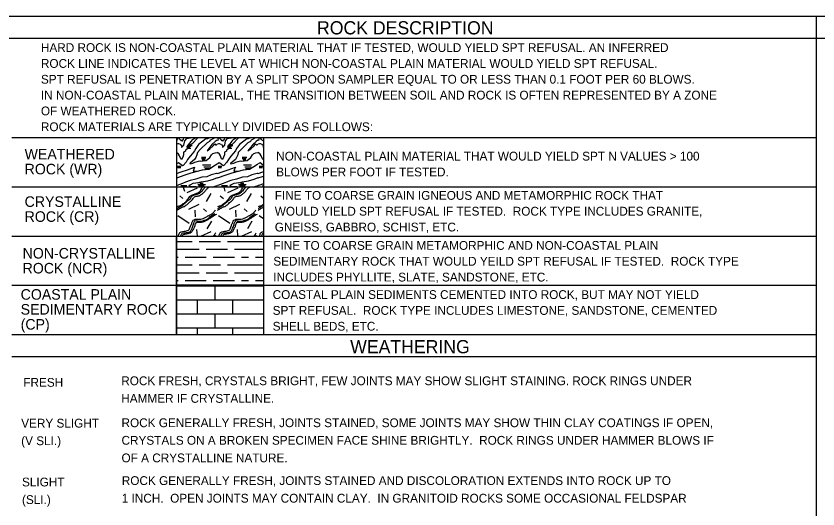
# Model space of a CAD drawing. Extents: x 278710 to 279187, y 171464 to 171625.
# Drawn here: x 279081.88 to 279121.42, y 171541.71 to 171566.02 of the extents above; entities that cross this region are included whole.
import ezdxf

# ---------------------------------------------------------------- set-up
doc = ezdxf.new("R2010")
doc.units = 0
doc.layers.add('Prop Strc Sect_ Misc - User Comment (Tx - small)', color=7, linetype='Continuous')

msp = doc.modelspace()

# ---------------------------------------------------------------- linework, layer by layer
at = {"layer": 'Prop Strc Sect_ Misc - User Comment (Tx - small)'}
for p, q in [((279005.33, 171566.02), (279158.027, 171566.02)), ((279121.332, 171566.02), (279121.332, 171485.806)), ((279005.33, 171564.936), (279158.027, 171564.936)), ((279121.332, 171560.012), (279081.678, 171560.012)), ((279089.795, 171560.012), (279089.795, 171550.295)), ((279090.164, 171560.005), (279090.167, 171560.012)), ((279090.484, 171560.005), (279090.492, 171560.012)), ((279090.844, 171560.005), (279090.853, 171560.012)), ((279092.176, 171560.005), (279092.179, 171560.012)), ((279092.496, 171560.005), (279092.504, 171560.012)), ((279092.856, 171560.005), (279092.865, 171560.012)), ((279094.081, 171560.012), (279094.081, 171550.295)), ((279090.31, 171559.559), (279090.458, 171559.559)), ((279090.323, 171559.603), (279090.495, 171559.603)), ((279090.324, 171559.51), (279090.504, 171559.51)), ((279090.348, 171559.641), (279090.562, 171559.641)), ((279092.322, 171559.559), (279092.47, 171559.559)), ((279092.335, 171559.603), (279092.507, 171559.603)), ((279092.336, 171559.51), (279092.516, 171559.51)), ((279092.36, 171559.641), (279092.574, 171559.641)), ((279091.024, 171559.06), (279091.244, 171559.06)), ((279091.024, 171558.993), (279091.224, 171558.993)), ((279091.064, 171558.925), (279091.204, 171558.925)), ((279093.036, 171559.06), (279093.256, 171559.06)), ((279093.036, 171558.993), (279093.236, 171558.993)), ((279093.076, 171558.925), (279093.216, 171558.925)), ((279089.844, 171558.61), (279090.024, 171558.61)), ((279089.844, 171558.543), (279090.004, 171558.543)), ((279091.084, 171558.678), (279091.484, 171558.678)), ((279091.144, 171558.588), (279091.464, 171558.588)), ((279091.184, 171558.498), (279091.404, 171558.498)), ((279091.856, 171558.61), (279092.036, 171558.61)), ((279091.856, 171558.543), (279092.016, 171558.543)), ((279093.096, 171558.678), (279093.496, 171558.678)), ((279093.156, 171558.588), (279093.476, 171558.588)), ((279093.196, 171558.498), (279093.416, 171558.498)), ((279093.868, 171558.61), (279094.048, 171558.61)), ((279093.868, 171558.543), (279094.028, 171558.543)), ((279090.844, 171557.719), (279091.219, 171557.719)), ((279090.944, 171557.778), (279091.104, 171557.778)), ((279092.856, 171557.719), (279093.231, 171557.719)), ((279092.956, 171557.778), (279093.116, 171557.778)), ((279121.332, 171557.583), (279081.678, 171557.583)), ((279089.985, 171557.604), (279090.379, 171557.604)), ((279090.004, 171557.665), (279090.304, 171557.665)), ((279090.884, 171557.643), (279091.164, 171557.643)), ((279091.997, 171557.604), (279092.391, 171557.604)), ((279092.016, 171557.665), (279092.316, 171557.665)), ((279092.896, 171557.643), (279093.176, 171557.643)), ((279094.009, 171557.604), (279094.081, 171557.604)), ((279094.028, 171557.665), (279094.081, 171557.665)), ((279094.081, 171556.679), (279093.977, 171556.614)), ((279121.332, 171555.154), (279081.678, 171555.154)), ((279091.725, 171555.218), (279091.691, 171555.158)), ((279093.725, 171555.218), (279093.691, 171555.158)), ((279094.081, 171555.187), (279094.065, 171555.158)), ((279089.791, 171554.902), (279089.877, 171554.902)), ((279089.877, 171554.902), (279090.571, 171554.902)), ((279090.918, 171554.902), (279091.96, 171554.902)), ((279092.307, 171554.902), (279093.348, 171554.902)), ((279093.348, 171554.902), (279094.042, 171554.902)), ((279089.791, 171554.52), (279089.877, 171554.52)), ((279089.877, 171554.52), (279090.918, 171554.52)), ((279091.265, 171554.52), (279092.307, 171554.52)), ((279092.654, 171554.52), (279093.348, 171554.52)), ((279093.348, 171554.52), (279094.076, 171554.52)), ((279089.791, 171554.134), (279089.873, 171554.134)), ((279089.791, 171553.748), (279089.877, 171553.748)), ((279089.877, 171553.748), (279090.571, 171553.748)), ((279090.22, 171554.134), (279091.261, 171554.134)), ((279090.918, 171553.748), (279091.96, 171553.748)), ((279091.608, 171554.134), (279092.649, 171554.134)), ((279092.307, 171553.748), (279093.348, 171553.748)), ((279092.996, 171554.134), (279093.343, 171554.134)), ((279093.348, 171553.748), (279094.042, 171553.748)), ((279093.69, 171554.134), (279094.076, 171554.134)), ((279089.791, 171553.362), (279089.877, 171553.362)), ((279089.877, 171553.362), (279090.918, 171553.362)), ((279091.265, 171553.362), (279092.307, 171553.362)), ((279092.654, 171553.362), (279093.348, 171553.362)), ((279093.348, 171553.362), (279094.076, 171553.362)), ((279089.791, 171552.976), (279089.873, 171552.976)), ((279090.22, 171552.976), (279091.261, 171552.976)), ((279091.608, 171552.976), (279092.649, 171552.976)), ((279092.996, 171552.976), (279093.343, 171552.976)), ((279093.69, 171552.976), (279094.076, 171552.976)), ((279121.332, 171552.724), (279081.678, 171552.724)), ((279091.704, 171552.026), (279091.704, 171552.711)), ((279089.795, 171552.026), (279094.081, 171552.026)), ((279090.836, 171551.332), (279090.836, 171552.026)), ((279092.571, 171551.332), (279092.571, 171552.026)), ((279089.795, 171551.332), (279094.081, 171551.332)), ((279091.704, 171550.638), (279091.704, 171551.332)), ((279089.795, 171550.638), (279094.081, 171550.638)), ((279090.836, 171550.295), (279090.836, 171550.638)), ((279092.571, 171550.295), (279092.571, 171550.638)), ((279121.332, 171550.295), (279081.678, 171550.295)), ((279121.332, 171549.21), (279081.678, 171549.21))]:
    msp.add_line(p, q, dxfattribs=at)
for points in [[(279089.8, 171559.897), (279089.85, 171559.925), (279089.841, 171559.984), (279089.831, 171560.012)], [(279089.987, 171559.685), (279089.909, 171559.724), (279089.855, 171559.724), (279089.8, 171559.7)], [(279090.844, 171560.005), (279090.564, 171559.713), (279090.504, 171559.668), (279090.364, 171559.668), (279090.304, 171559.578), (279090.324, 171559.51), (279090.344, 171559.465), (279090.244, 171559.398), (279090.244, 171559.353), (279090.244, 171559.353), (279090.184, 171559.33), (279090.144, 171559.308), (279090.144, 171559.173), (279090.104, 171559.06), (279090.044, 171558.948), (279090.004, 171558.97), (279089.944, 171559.128), (279089.898, 171559.213)], [(279089.964, 171559.938), (279089.924, 171559.983), (279089.924, 171560.012)], [(279089.964, 171559.938), (279089.984, 171559.915), (279090.024, 171559.87), (279090.044, 171559.915), (279090.064, 171559.87), (279090.084, 171559.87), (279090.104, 171559.915), (279090.144, 171559.938), (279090.164, 171560.005)], [(279091.244, 171559.96), (279090.884, 171559.69), (279090.744, 171559.488), (279090.684, 171559.375), (279090.584, 171559.24), (279090.464, 171559.105), (279090.344, 171558.948), (279090.264, 171558.813), (279090.124, 171558.655), (279090.084, 171558.633), (279089.964, 171558.723)], [(279089.987, 171559.685), (279090.044, 171559.645), (279090.044, 171559.533), (279090.164, 171559.645), (279090.204, 171559.87), (279090.304, 171559.983), (279090.484, 171560.005)], [(279090.728, 171560.012), (279090.699, 171559.986), (279090.661, 171559.967), (279090.571, 171559.91), (279090.512, 171559.849), (279090.421, 171559.739), (279090.364, 171559.668)], [(279091.324, 171559.78), (279090.964, 171559.443), (279090.824, 171559.285), (279090.804, 171559.173), (279090.744, 171559.038), (279090.684, 171558.948), (279090.464, 171558.768), (279090.444, 171558.745), (279090.464, 171558.723), (279090.604, 171558.768), (279090.704, 171558.813), (279090.944, 171558.88), (279090.964, 171558.858), (279091.264, 171558.903), (279091.444, 171559.038), (279091.522, 171559.178)], [(279091.244, 171559.96), (279091.282, 171559.975), (279091.338, 171559.987), (279091.407, 171560.009), (279091.411, 171560.012)], [(279091.8, 171559.897), (279091.704, 171559.825), (279091.544, 171559.69), (279091.444, 171559.555), (279091.304, 171559.375), (279091.444, 171559.465), (279091.604, 171559.623), (279091.684, 171559.713), (279091.724, 171559.668), (279091.764, 171559.668), (279091.8, 171559.7)], [(279091.324, 171559.78), (279091.444, 171559.848), (279091.484, 171559.915), (279091.604, 171559.983), (279091.644, 171560.005)], [(279091.644, 171560.005), (279091.658, 171560.012)], [(279091.812, 171559.897), (279091.862, 171559.925), (279091.853, 171559.984), (279091.843, 171560.012)], [(279091.999, 171559.685), (279091.921, 171559.724), (279091.867, 171559.724), (279091.812, 171559.7)], [(279092.856, 171560.005), (279092.576, 171559.713), (279092.516, 171559.668), (279092.376, 171559.668), (279092.316, 171559.578), (279092.336, 171559.51), (279092.356, 171559.465), (279092.256, 171559.398), (279092.256, 171559.353), (279092.256, 171559.353), (279092.196, 171559.33), (279092.156, 171559.308), (279092.156, 171559.173), (279092.116, 171559.06), (279092.056, 171558.948), (279092.016, 171558.97), (279091.956, 171559.128), (279091.91, 171559.213)], [(279091.976, 171559.938), (279091.936, 171559.983), (279091.936, 171560.012)], [(279091.976, 171559.938), (279091.996, 171559.915), (279092.036, 171559.87), (279092.056, 171559.915), (279092.076, 171559.87), (279092.096, 171559.87), (279092.116, 171559.915), (279092.156, 171559.938), (279092.176, 171560.005)], [(279093.256, 171559.96), (279092.896, 171559.69), (279092.756, 171559.488), (279092.696, 171559.375), (279092.596, 171559.24), (279092.476, 171559.105), (279092.356, 171558.948), (279092.276, 171558.813), (279092.136, 171558.655), (279092.096, 171558.633), (279091.976, 171558.723)], [(279091.999, 171559.685), (279092.056, 171559.645), (279092.056, 171559.533), (279092.176, 171559.645), (279092.216, 171559.87), (279092.316, 171559.983), (279092.496, 171560.005)], [(279092.74, 171560.012), (279092.711, 171559.986), (279092.673, 171559.967), (279092.583, 171559.91), (279092.524, 171559.849), (279092.433, 171559.739), (279092.376, 171559.668)], [(279093.336, 171559.78), (279092.976, 171559.443), (279092.836, 171559.285), (279092.816, 171559.173), (279092.756, 171559.038), (279092.696, 171558.948), (279092.476, 171558.768), (279092.456, 171558.745), (279092.476, 171558.723), (279092.616, 171558.768), (279092.716, 171558.813), (279092.956, 171558.88), (279092.976, 171558.858), (279093.276, 171558.903), (279093.456, 171559.038), (279093.534, 171559.178)], [(279093.256, 171559.96), (279093.294, 171559.975), (279093.35, 171559.987), (279093.419, 171560.009), (279093.423, 171560.012)], [(279093.812, 171559.897), (279093.716, 171559.825), (279093.556, 171559.69), (279093.456, 171559.555), (279093.316, 171559.375), (279093.456, 171559.465), (279093.616, 171559.623), (279093.696, 171559.713), (279093.736, 171559.668), (279093.776, 171559.668), (279093.812, 171559.7)], [(279093.336, 171559.78), (279093.456, 171559.848), (279093.496, 171559.915), (279093.616, 171559.983), (279093.656, 171560.005)], [(279093.656, 171560.005), (279093.67, 171560.012)], [(279093.824, 171559.897), (279093.874, 171559.925), (279093.865, 171559.984), (279093.855, 171560.012)], [(279094.011, 171559.685), (279093.933, 171559.724), (279093.879, 171559.724), (279093.824, 171559.7)], [(279093.988, 171559.938), (279093.948, 171559.983), (279093.948, 171560.012)], [(279093.988, 171559.938), (279094.008, 171559.915), (279094.048, 171559.87), (279094.068, 171559.915), (279094.081, 171559.885)], [(279094.011, 171559.685), (279094.068, 171559.645), (279094.068, 171559.533), (279094.081, 171559.545)], [(279089.898, 171559.213), (279089.799, 171559.293)], [(279091.522, 171559.178), (279091.588, 171559.244), (279091.701, 171559.274), (279091.799, 171559.293)], [(279091.91, 171559.213), (279091.811, 171559.293)], [(279093.534, 171559.178), (279093.6, 171559.244), (279093.713, 171559.274), (279093.811, 171559.293)], [(279093.922, 171559.213), (279093.823, 171559.293)], [(279094.081, 171558.972), (279094.068, 171558.948), (279094.028, 171558.97), (279093.968, 171559.128), (279093.922, 171559.213)], [(279089.964, 171558.723), (279089.89, 171558.779), (279089.8, 171558.733)], [(279089.8, 171558.259), (279090.027, 171558.338), (279090.33, 171558.436), (279090.687, 171558.559), (279090.643, 171558.461), (279090.609, 171558.377), (279090.829, 171558.373)], [(279089.804, 171558.048), (279090.224, 171558.183), (279090.524, 171558.295), (279091.084, 171558.43), (279091.384, 171558.475), (279091.724, 171558.678), (279091.8, 171558.733)], [(279091.976, 171558.723), (279091.902, 171558.779), (279091.812, 171558.733)], [(279091.812, 171558.259), (279092.039, 171558.338), (279092.342, 171558.436), (279092.699, 171558.559), (279092.655, 171558.461), (279092.621, 171558.377), (279092.841, 171558.373)], [(279091.816, 171558.048), (279092.236, 171558.183), (279092.536, 171558.295), (279093.096, 171558.43), (279093.396, 171558.475), (279093.736, 171558.678), (279093.812, 171558.733)], [(279093.988, 171558.723), (279093.914, 171558.779), (279093.824, 171558.733)], [(279094.081, 171558.653), (279093.988, 171558.723)], [(279091.8, 171558.259), (279091.764, 171558.25), (279091.504, 171558.183), (279091.284, 171558.093), (279091.044, 171558.07), (279090.744, 171557.98), (279090.464, 171557.913), (279090.244, 171557.823), (279090.084, 171557.755), (279089.824, 171557.665), (279089.804, 171557.665)], [(279093.812, 171558.259), (279093.776, 171558.25), (279093.516, 171558.183), (279093.296, 171558.093), (279093.056, 171558.07), (279092.756, 171557.98), (279092.476, 171557.913), (279092.256, 171557.823), (279092.096, 171557.755), (279091.836, 171557.665), (279091.816, 171557.665)], [(279093.824, 171558.259), (279094.051, 171558.338), (279094.081, 171558.347)], [(279093.828, 171558.048), (279094.081, 171558.129)], [(279089.795, 171558.05), (279089.799, 171558.052)], [(279090.822, 171557.8), (279090.744, 171557.778), (279090.604, 171557.755), (279090.484, 171557.688), (279090.404, 171557.665), (279090.424, 171557.643), (279090.524, 171557.62), (279090.704, 171557.62), (279090.764, 171557.62), (279090.78, 171557.583)], [(279090.822, 171557.8), (279091.013, 171557.841), (279091.332, 171557.9), (279091.616, 171557.973), (279091.811, 171558.052)], [(279092.834, 171557.8), (279092.756, 171557.778), (279092.616, 171557.755), (279092.496, 171557.688), (279092.416, 171557.665), (279092.436, 171557.643), (279092.536, 171557.62), (279092.716, 171557.62), (279092.776, 171557.62), (279092.792, 171557.583)], [(279092.834, 171557.8), (279093.025, 171557.841), (279093.344, 171557.9), (279093.628, 171557.973), (279093.823, 171558.052)], [(279094.081, 171557.745), (279093.848, 171557.665), (279093.828, 171557.665)], [(279090.122, 171557.583), (279090.185, 171557.386)], [(279090.324, 171557.319), (279090.832, 171557.555)], [(279091.571, 171557.583), (279091.65, 171557.606), (279091.804, 171557.665)], [(279092.122, 171557.583), (279092.185, 171557.386)], [(279092.324, 171557.319), (279092.832, 171557.555)], [(279093.583, 171557.583), (279093.662, 171557.606), (279093.816, 171557.665)], [(279089.954, 171557.151), (279090.11, 171557.015)], [(279091.482, 171557.265), (279091.254, 171556.877)], [(279091.954, 171557.151), (279092.11, 171557.015)], [(279093.482, 171557.265), (279093.254, 171556.877)], [(279093.954, 171557.151), (279094.081, 171557.04)], [(279090.402, 171556.503), (279090.91, 171556.739)], [(279091.124, 171556.518), (279091.28, 171556.382)], [(279092.402, 171556.503), (279092.91, 171556.739)], [(279093.124, 171556.518), (279093.28, 171556.382)], [(279089.867, 171556.186), (279090.423, 171555.802)], [(279090.696, 171556.451), (279090.72, 171556.119)], [(279091.867, 171556.186), (279092.423, 171555.802)], [(279092.696, 171556.451), (279092.72, 171556.119)], [(279093.867, 171556.186), (279094.081, 171556.038)], [(279091.516, 171555.911), (279091.288, 171555.523)], [(279093.516, 171555.911), (279093.288, 171555.523)], [(279090.783, 171555.488), (279090.807, 171555.158)], [(279091, 171555.159), (279091.508, 171555.395)], [(279092.783, 171555.488), (279092.807, 171555.158)], [(279093, 171555.159), (279093.508, 171555.395)]]:
    msp.add_lwpolyline(points, dxfattribs=at)
for points in [[(279089.791, 171555.158), (279094.076, 171555.158), (279094.076, 171552.742), (279089.791, 171552.742)], [(279089.795, 171552.711), (279094.081, 171552.711), (279094.081, 171550.295), (279089.795, 171550.295)]]:
    msp.add_lwpolyline(points, close=True, dxfattribs=at)
for points in [[(279089.837, 171556.63), (279089.997, 171556.682), (279090.165, 171556.798), (279090.289, 171556.906), (279090.313, 171556.942), (279090.393, 171557.026), (279090.445, 171557.118), (279090.545, 171557.19), (279090.637, 171557.226), (279090.797, 171557.282), (279090.893, 171557.33), (279091.001, 171557.45), (279091.049, 171557.55), (279091.071, 171557.583)], [(279091.188, 171557.583), (279091.157, 171557.522), (279091.077, 171557.43), (279091.005, 171557.342), (279090.893, 171557.258), (279090.793, 171557.214), (279090.673, 171557.178), (279090.605, 171557.162), (279090.529, 171557.114), (279090.505, 171557.066), (279090.461, 171556.99), (279090.337, 171556.898), (279090.253, 171556.822), (279090.177, 171556.754), (279090.085, 171556.682), (279089.977, 171556.614)], [(279090.133, 171556.606), (279090.301, 171556.714), (279090.449, 171556.85), (279090.589, 171556.978), (279090.689, 171557.11), (279090.829, 171557.142), (279090.981, 171557.19), (279091.101, 171557.282), (279091.205, 171557.378), (279091.253, 171557.454)], [(279091.253, 171557.454), (279091.349, 171557.546), (279091.404, 171557.583)], [(279091.837, 171556.63), (279091.997, 171556.682), (279092.165, 171556.798), (279092.289, 171556.906), (279092.313, 171556.942), (279092.393, 171557.026), (279092.445, 171557.118), (279092.545, 171557.19), (279092.637, 171557.226), (279092.797, 171557.282), (279092.893, 171557.33), (279093.001, 171557.45), (279093.049, 171557.55), (279093.071, 171557.583)], [(279093.188, 171557.583), (279093.157, 171557.522), (279093.077, 171557.43), (279093.005, 171557.342), (279092.893, 171557.258), (279092.793, 171557.214), (279092.673, 171557.178), (279092.605, 171557.162), (279092.529, 171557.114), (279092.505, 171557.066), (279092.461, 171556.99), (279092.337, 171556.898), (279092.253, 171556.822), (279092.177, 171556.754), (279092.085, 171556.682), (279091.977, 171556.614)], [(279092.133, 171556.606), (279092.301, 171556.714), (279092.449, 171556.85), (279092.589, 171556.978), (279092.689, 171557.11), (279092.829, 171557.142), (279092.981, 171557.19), (279093.101, 171557.282), (279093.205, 171557.378), (279093.253, 171557.454)], [(279093.253, 171557.454), (279093.349, 171557.546), (279093.404, 171557.583)], [(279089.977, 171556.614), (279089.877, 171556.554), (279089.817, 171556.51)], [(279090.133, 171556.606), (279089.977, 171556.53), (279089.817, 171556.434)], [(279091.977, 171556.614), (279091.877, 171556.554), (279091.817, 171556.51)], [(279092.133, 171556.606), (279091.977, 171556.53), (279091.817, 171556.434)], [(279093.977, 171556.614), (279093.877, 171556.554), (279093.817, 171556.51)], [(279094.081, 171556.582), (279093.977, 171556.53), (279093.817, 171556.434)], [(279093.837, 171556.63), (279093.997, 171556.682), (279094.081, 171556.735)], [(279090.545, 171555.786), (279090.557, 171555.822), (279090.617, 171555.946), (279090.717, 171555.994), (279090.905, 171556.002), (279091.065, 171556.018), (279091.209, 171556.086), (279091.345, 171556.158), (279091.529, 171556.266)], [(279090.645, 171555.786), (279090.645, 171555.798), (279090.669, 171555.854), (279090.713, 171555.918), (279090.861, 171555.906), (279091.017, 171555.91), (279091.153, 171555.946), (279091.309, 171556.006), (279091.489, 171556.15), (279091.681, 171556.282)], [(279091.768, 171556.239), (279091.568, 171556.119), (279091.444, 171556.035), (279091.308, 171555.955), (279091.176, 171555.883), (279091.012, 171555.843), (279090.864, 171555.831), (279090.792, 171555.831), (279090.744, 171555.819), (279090.724, 171555.759)], [(279091.529, 171556.266), (279091.629, 171556.346), (279091.713, 171556.458)], [(279092.545, 171555.786), (279092.557, 171555.822), (279092.617, 171555.946), (279092.717, 171555.994), (279092.905, 171556.002), (279093.065, 171556.018), (279093.209, 171556.086), (279093.345, 171556.158), (279093.529, 171556.266)], [(279092.645, 171555.786), (279092.645, 171555.798), (279092.669, 171555.854), (279092.713, 171555.918), (279092.861, 171555.906), (279093.017, 171555.91), (279093.153, 171555.946), (279093.309, 171556.006), (279093.489, 171556.15), (279093.681, 171556.282)], [(279093.768, 171556.239), (279093.568, 171556.119), (279093.444, 171556.035), (279093.308, 171555.955), (279093.176, 171555.883), (279093.012, 171555.843), (279092.864, 171555.831), (279092.792, 171555.831), (279092.744, 171555.819), (279092.724, 171555.759)], [(279093.529, 171556.266), (279093.629, 171556.346), (279093.713, 171556.458)], [(279089.876, 171555.158), (279089.901, 171555.218), (279089.965, 171555.346), (279090.089, 171555.398), (279090.241, 171555.414), (279090.421, 171555.498), (279090.485, 171555.654), (279090.545, 171555.786)], [(279089.978, 171555.158), (279090.001, 171555.19), (279090.077, 171555.31), (279090.169, 171555.322), (279090.337, 171555.346), (279090.449, 171555.374), (279090.533, 171555.498), (279090.585, 171555.614), (279090.617, 171555.71), (279090.645, 171555.786)], [(279090.725, 171555.761), (279090.721, 171555.757), (279090.693, 171555.673), (279090.625, 171555.517), (279090.549, 171555.385), (279090.465, 171555.309), (279090.353, 171555.273), (279090.213, 171555.253), (279090.149, 171555.241), (279090.093, 171555.205), (279090.065, 171555.158)], [(279091.876, 171555.158), (279091.901, 171555.218), (279091.965, 171555.346), (279092.089, 171555.398), (279092.241, 171555.414), (279092.421, 171555.498), (279092.485, 171555.654), (279092.545, 171555.786)], [(279091.978, 171555.158), (279092.001, 171555.19), (279092.077, 171555.31), (279092.169, 171555.322), (279092.337, 171555.346), (279092.449, 171555.374), (279092.533, 171555.498), (279092.585, 171555.614), (279092.617, 171555.71), (279092.645, 171555.786)], [(279092.725, 171555.761), (279092.721, 171555.757), (279092.693, 171555.673), (279092.625, 171555.517), (279092.549, 171555.385), (279092.465, 171555.309), (279092.353, 171555.273), (279092.213, 171555.253), (279092.149, 171555.241), (279092.093, 171555.205), (279092.065, 171555.158)], [(279091.617, 171555.158), (279091.641, 171555.194), (279091.729, 171555.334)], [(279093.617, 171555.158), (279093.641, 171555.194), (279093.729, 171555.334)], [(279093.876, 171555.158), (279093.901, 171555.218), (279093.965, 171555.346), (279094.081, 171555.396)], [(279093.978, 171555.158), (279094.001, 171555.19), (279094.077, 171555.31), (279094.081, 171555.311)]]:
    msp.add_spline(points, degree=3, dxfattribs=at)

# ---------------------------------------------------------------- texts
for s, height, p in [('ROCK DESCRIPTION', 0.6507, (279096.723, 171565.114)), ('HARD ROCK IS NON-COASTAL PLAIN MATERIAL THAT IF TESTED, WOULD YIELD SPT REFUSAL. AN INFERRED ', 0.43381, (279083.11, 171564.246)), ('ROCK LINE INDICATES THE LEVEL AT WHICH NON-COASTAL PLAIN MATERIAL WOULD YIELD SPT REFUSAL.  ', 0.43381, (279083.11, 171563.465)), ('SPT REFUSAL IS PENETRATION BY A SPLIT SPOON SAMPLER EQUAL TO OR LESS THAN 0.1 FOOT PER 60 BLOWS.  ', 0.43381, (279083.11, 171562.684)), ('IN NON-COASTAL PLAIN MATERIAL, THE TRANSITION BETWEEN SOIL AND ROCK IS OFTEN REPRESENTED BY A ZONE ', 0.43381, (279083.11, 171561.903)), ('OF WEATHERED ROCK.  ', 0.43381, (279083.11, 171561.123)), ('ROCK MATERIALS ARE TYPICALLY DIVIDED AS FOLLOWS:', 0.43381, (279083.11, 171560.342)), ('WEATHERED', 0.5206, (279082.307, 171558.949)), ('NON-COASTAL PLAIN MATERIAL THAT WOULD YIELD SPT N VALUES > 100', 0.43381, (279094.71, 171558.893)), ('ROCK (WR)', 0.5206, (279082.307, 171558.212)), ('BLOWS PER FOOT IF TESTED.', 0.43381, (279094.71, 171558.112)), ('FINE TO COARSE GRAIN IGNEOUS AND METAMORPHIC ROCK THAT ', 0.43381, (279094.64, 171556.958)), ('CRYSTALLINE', 0.52056, (279082.307, 171556.607)), ('WOULD YIELD SPT REFUSAL IF TESTED.  ROCK TYPE INCLUDES GRANITE, ', 0.43381, (279094.64, 171556.177)), ('ROCK (CR)', 0.5206, (279082.307, 171555.869)), ('GNEISS, GABBRO, SCHIST, ETC.', 0.43381, (279094.64, 171555.396)), ('FINE TO COARSE GRAIN METAMORPHIC AND NON-COASTAL PLAIN ', 0.43381, (279094.567, 171554.49)), ('NON-CRYSTALLINE', 0.52056, (279082.208, 171554.06)), ('SEDIMENTARY ROCK THAT WOULD YEILD SPT REFUSAL IF TESTED.  ROCK TYPE ', 0.43381, (279094.567, 171553.709)), ('ROCK (NCR)', 0.5206, (279082.208, 171553.323)), ('INCLUDES PHYLLITE, SLATE, SANDSTONE, ETC.', 0.43381, (279094.567, 171552.928)), ('COASTAL PLAIN', 0.52056, (279082.112, 171552.03)), ('COASTAL PLAIN SEDIMENTS CEMENTED INTO ROCK, BUT MAY NOT YIELD ', 0.43381, (279094.536, 171552.065)), ('SEDIMENTARY ROCK', 0.52056, (279082.112, 171551.293)), ('SPT REFUSAL.  ROCK TYPE INCLUDES LIMESTONE, SANDSTONE, CEMENTED ', 0.43381, (279094.536, 171551.284)), ('(CP)', 0.5206, (279082.112, 171550.555)), ('SHELL BEDS, ETC.', 0.43381, (279094.536, 171550.503)), ('WEATHERING', 0.6507, (279098.358, 171549.388)), ('ROCK FRESH, CRYSTALS BRIGHT, FEW JOINTS MAY SHOW SLIGHT STAINING. ROCK RINGS UNDER ', 0.43381, (279087.071, 171547.814)), ('FRESH', 0.4338, (279082.242, 171547.736)), ('HAMMER IF CRYSTALLINE.', 0.43381, (279087.071, 171546.946)), ('VERY SLIGHT ', 0.43381, (279082.138, 171545.723)), ('ROCK GENERALLY FRESH, JOINTS STAINED, SOME JOINTS MAY SHOW THIN CLAY COATINGS IF OPEN, ', 0.43381, (279087.084, 171545.744)), ('(V SLI.)', 0.4338, (279082.138, 171544.856)), ('CRYSTALS ON A BROKEN SPECIMEN FACE SHINE BRIGHTLY.  ROCK RINGS UNDER HAMMER BLOWS IF ', 0.43381, (279087.084, 171544.877)), ('OF A CRYSTALLINE NATURE.', 0.43381, (279087.084, 171544.01)), ('SLIGHT', 0.4338, (279082.177, 171542.821)), ('ROCK GENERALLY FRESH, JOINTS STAINED AND DISCOLORATION EXTENDS INTO ROCK UP TO ', 0.43381, (279087.097, 171542.89)), ('(SLI.)', 0.4338, (279082.177, 171541.953)), ('1 INCH.  OPEN JOINTS MAY CONTAIN CLAY.  IN GRANITOID ROCKS SOME OCCASIONAL FELDSPAR ', 0.43381, (279087.097, 171542.022))]:
    msp.add_text(s, height=height, dxfattribs=at).set_placement(p)

doc.saveas('drawing.dxf')
